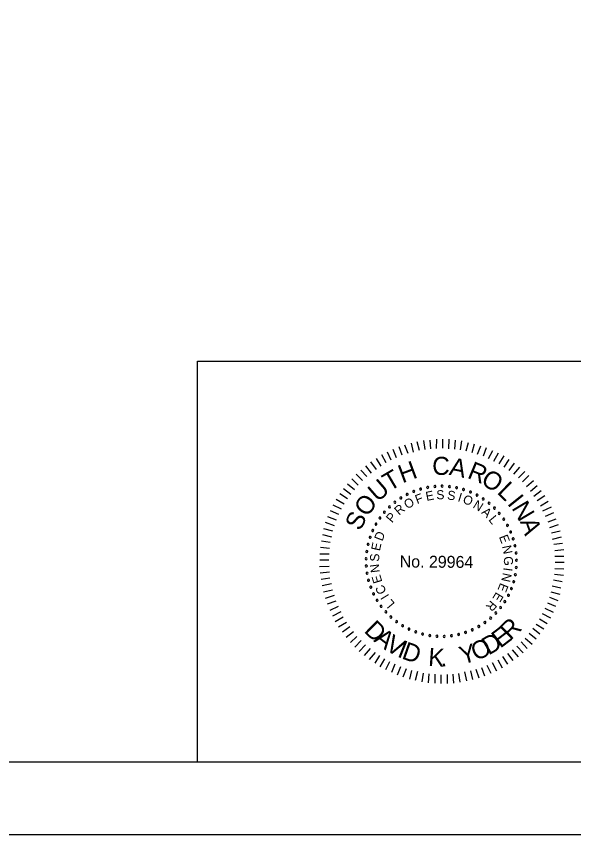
# Model space of a CAD drawing. Extents: x -121.2 to -24.9, y 6.4 to 66.3.
# Drawn here: x -64.11 to -53.92, y 6.35 to 21.33 of the extents above; entities that cross this region are included whole.
import ezdxf

# ---------------------------------------------------------------- set-up
doc = ezdxf.new("R2010")
doc.units = 0
for name, color, linetype in [('BR_BORDER LINES', 7, 'Continuous'), ('BR_TEXT', 7, 'Continuous'), ('Level 31', 7, 'Continuous')]:
    doc.layers.add(name, color=color, linetype=linetype)

msp = doc.modelspace()

# ---------------------------------------------------------------- linework, layer by layer
at = {"layer": 'BR_BORDER LINES'}
for p, q in [((-60.804, 15.017), (-46.496, 15.017)), ((-60.804, 7.683), (-60.804, 15.017)), ((-116.272, 7.683), (-26.496, 7.683))]:
    msp.add_line(p, q, dxfattribs=at)
at = {"layer": 'BR_TEXT'}
for p, q in [((-56.951, 13.326), (-57.009, 13.479)), ((-56.854, 13.352), (-56.89, 13.515)), ((-56.744, 13.379), (-56.782, 13.537)), ((-56.639, 13.398), (-56.663, 13.561)), ((-56.534, 13.409), (-56.544, 13.572)), ((-56.428, 13.415), (-56.427, 13.587)), ((-56.316, 13.421), (-56.315, 13.586)), ((-56.204, 13.413), (-56.198, 13.585)), ((-56.097, 13.405), (-56.084, 13.568)), ((-55.994, 13.393), (-55.965, 13.555)), ((-55.886, 13.372), (-55.848, 13.529)), ((-55.777, 13.343), (-55.734, 13.505)), ((-57.258, 13.202), (-57.328, 13.351)), ((-57.16, 13.247), (-57.223, 13.396)), ((-57.056, 13.292), (-57.112, 13.448)), ((-55.679, 13.315), (-55.62, 13.468)), ((-55.574, 13.28), (-55.515, 13.435)), ((-55.478, 13.233), (-55.403, 13.381)), ((-55.382, 13.187), (-55.298, 13.335)), ((-57.445, 13.092), (-57.526, 13.236)), ((-57.35, 13.155), (-57.432, 13.3)), ((-55.282, 13.138), (-55.196, 13.281)), ((-55.193, 13.073), (-55.103, 13.216)), ((-57.617, 12.967), (-57.724, 13.101)), ((-57.528, 13.035), (-57.632, 13.171)), ((-55.104, 13.015), (-55.007, 13.149)), ((-55.018, 12.946), (-54.909, 13.078)), ((-57.783, 12.829), (-57.901, 12.947)), ((-57.705, 12.902), (-57.816, 13.021)), ((-54.934, 12.879), (-54.818, 12.997)), ((-54.859, 12.805), (-54.743, 12.921)), ((-57.929, 12.663), (-58.061, 12.767)), ((-57.862, 12.747), (-57.978, 12.86)), ((-54.784, 12.722), (-54.657, 12.833)), ((-54.712, 12.636), (-54.587, 12.738)), ((-58.056, 12.497), (-58.2, 12.585)), ((-57.998, 12.574), (-58.13, 12.681)), ((-54.648, 12.547), (-54.517, 12.651)), ((-58.121, 12.399), (-58.264, 12.485)), ((-54.589, 12.468), (-54.449, 12.554)), ((-54.531, 12.37), (-54.388, 12.453)), ((-58.168, 12.308), (-58.318, 12.382)), ((-54.483, 12.278), (-54.329, 12.35)), ((-58.261, 12.107), (-58.416, 12.166)), ((-58.214, 12.21), (-58.367, 12.278)), ((-54.436, 12.179), (-54.284, 12.244)), ((-54.391, 12.075), (-54.24, 12.131)), ((-58.294, 12), (-58.458, 12.061)), ((-54.355, 11.968), (-54.202, 12.026)), ((-58.346, 11.792), (-58.512, 11.835)), ((-58.326, 11.904), (-58.489, 11.945)), ((-54.329, 11.871), (-54.168, 11.909)), ((-58.374, 11.696), (-58.536, 11.718)), ((-54.307, 11.759), (-54.146, 11.799)), ((-54.285, 11.663), (-54.127, 11.682)), ((-58.386, 11.587), (-58.551, 11.606)), ((-54.267, 11.553), (-54.105, 11.57)), ((-58.394, 11.481), (-58.566, 11.483)), ((-54.264, 11.447), (-54.103, 11.446)), ((-58.396, 11.257), (-58.568, 11.254)), ((-58.4, 11.372), (-58.567, 11.373)), ((-54.258, 11.338), (-54.095, 11.336)), ((-58.39, 11.154), (-58.555, 11.135)), ((-54.271, 11.12), (-54.109, 11.098)), ((-54.265, 11.223), (-54.105, 11.217)), ((-58.379, 11.044), (-58.542, 11.02)), ((-58.353, 10.939), (-58.52, 10.904)), ((-54.29, 11.011), (-54.132, 10.984)), ((-58.335, 10.826), (-58.498, 10.789)), ((-54.338, 10.793), (-54.178, 10.753)), ((-54.314, 10.905), (-54.154, 10.867)), ((-58.304, 10.728), (-58.469, 10.672)), ((-54.366, 10.695), (-54.213, 10.637)), ((-58.273, 10.625), (-58.429, 10.569)), ((-58.228, 10.526), (-58.382, 10.454)), ((-54.45, 10.495), (-54.3, 10.42)), ((-54.403, 10.593), (-54.253, 10.534)), ((-58.183, 10.429), (-58.335, 10.35)), ((-54.499, 10.399), (-54.346, 10.318)), ((-58.138, 10.331), (-58.283, 10.247)), ((-58.075, 10.232), (-58.22, 10.148)), ((-54.608, 10.203), (-54.469, 10.117)), ((-54.548, 10.301), (-54.407, 10.215)), ((-58.018, 10.153), (-58.152, 10.056)), ((-57.95, 10.064), (-58.084, 9.959)), ((-54.733, 10.037), (-54.61, 9.931)), ((-54.668, 10.126), (-54.539, 10.026)), ((-57.885, 9.974), (-58.002, 9.865)), ((-57.808, 9.904), (-57.927, 9.784)), ((-54.807, 9.948), (-54.682, 9.837)), ((-57.73, 9.824), (-57.844, 9.701)), ((-57.644, 9.754), (-57.753, 9.629)), ((-54.959, 9.801), (-54.846, 9.676)), ((-54.883, 9.88), (-54.77, 9.758)), ((-57.555, 9.685), (-57.662, 9.558)), ((-57.473, 9.627), (-57.557, 9.488)), ((-55.222, 9.608), (-55.134, 9.468)), ((-55.132, 9.665), (-55.037, 9.536)), ((-55.044, 9.733), (-54.938, 9.606)), ((-57.38, 9.567), (-57.464, 9.423)), ((-57.289, 9.513), (-57.361, 9.365)), ((-57.191, 9.467), (-57.256, 9.319)), ((-55.509, 9.453), (-55.437, 9.304)), ((-55.413, 9.498), (-55.331, 9.348)), ((-55.311, 9.55), (-55.228, 9.405)), ((-57.088, 9.42), (-57.147, 9.27)), ((-56.983, 9.387), (-57.044, 9.232)), ((-56.888, 9.354), (-56.925, 9.197)), ((-56.778, 9.335), (-56.818, 9.171)), ((-56.673, 9.305), (-56.699, 9.149)), ((-56.568, 9.292), (-56.58, 9.128)), ((-56.462, 9.285), (-56.464, 9.12)), ((-56.131, 9.289), (-56.121, 9.124)), ((-56.028, 9.299), (-56.001, 9.143)), ((-55.92, 9.328), (-55.884, 9.163)), ((-55.81, 9.346), (-55.77, 9.187)), ((-55.711, 9.377), (-55.655, 9.221)), ((-55.606, 9.408), (-55.55, 9.256)), ((-56.35, 9.277), (-56.352, 9.114)), ((-56.238, 9.283), (-56.235, 9.118))]:
    msp.add_line(p, q, dxfattribs=at)
for centre, start, end in [((-56.46, 12.723), 5.0653, 185.0653), ((-56.328, 12.728), 359.5268, 179.5268), ((-56.195, 12.72), 353.9884, 173.9884), ((-56.968, 12.577), 27.2191, 207.2191), ((-56.968, 12.577), 207.2191, 27.2191), ((-56.847, 12.632), 21.6807, 201.6807), ((-56.847, 12.632), 201.6807, 21.6807), ((-56.721, 12.674), 16.1422, 196.1422), ((-56.721, 12.674), 196.1422, 16.1422), ((-56.592, 12.705), 10.6038, 190.6038), ((-56.592, 12.705), 190.6038, 10.6038), ((-56.46, 12.723), 185.0653, 5.0653), ((-56.328, 12.728), 179.5268, 359.5268), ((-56.195, 12.72), 173.9884, 353.9884), ((-56.064, 12.699), 348.4499, 168.4499), ((-56.064, 12.699), 168.4499, 348.4499), ((-55.935, 12.666), 162.9114, 342.9114), ((-55.935, 12.666), 342.9114, 162.9114), ((-55.81, 12.621), 157.373, 337.373), ((-55.81, 12.621), 337.373, 157.373), ((-55.69, 12.564), 331.8345, 151.8345), ((-57.192, 12.434), 38.2961, 218.2961), ((-57.192, 12.434), 218.2961, 38.2961), ((-57.083, 12.511), 32.7576, 212.7576), ((-57.083, 12.511), 212.7576, 32.7576), ((-55.69, 12.564), 151.8345, 331.8345), ((-55.576, 12.495), 146.2961, 326.2961), ((-55.576, 12.495), 326.2961, 146.2961), ((-55.47, 12.416), 320.7576, 140.7576), ((-57.292, 12.347), 43.8345, 223.8345), ((-57.292, 12.347), 223.8345, 43.8345), ((-55.47, 12.416), 140.7576, 320.7576), ((-55.371, 12.327), 135.2191, 315.2191), ((-55.371, 12.327), 315.2191, 135.2191), ((-57.465, 12.145), 54.9114, 234.9114), ((-57.465, 12.145), 234.9114, 54.9114), ((-57.384, 12.25), 49.373, 229.373), ((-57.384, 12.25), 229.373, 49.373), ((-55.282, 12.229), 129.6807, 309.6807), ((-55.282, 12.229), 309.6807, 129.6807), ((-55.202, 12.122), 124.1422, 304.1422), ((-55.202, 12.122), 304.1422, 124.1422), ((-57.537, 12.033), 60.4499, 240.4499), ((-57.537, 12.033), 240.4499, 60.4499), ((-55.133, 12.009), 118.6038, 298.6038), ((-55.133, 12.009), 298.6038, 118.6038), ((-57.597, 11.915), 65.9884, 245.9884), ((-57.597, 11.915), 245.9884, 65.9884), ((-55.075, 11.889), 113.0653, 293.0653), ((-55.075, 11.889), 293.0653, 113.0653), ((-57.681, 11.663), 77.0653, 257.0653), ((-57.681, 11.663), 257.0653, 77.0653), ((-57.645, 11.791), 71.5268, 251.5268), ((-57.645, 11.791), 251.5268, 71.5268), ((-55.029, 11.764), 107.5268, 287.5268), ((-55.029, 11.764), 287.5268, 107.5268), ((-57.705, 11.532), 82.6038, 262.6038), ((-57.705, 11.532), 262.6038, 82.6038), ((-54.996, 11.636), 101.9884, 281.9884), ((-54.996, 11.636), 281.9884, 101.9884), ((-57.716, 11.4), 88.1422, 268.1422), ((-57.716, 11.4), 268.1422, 88.1422), ((-54.975, 11.504), 96.4499, 276.4499), ((-54.967, 11.372), 90.9114, 270.9114), ((-54.975, 11.504), 276.4499, 96.4499), ((-54.967, 11.372), 270.9114, 90.9114), ((-57.714, 11.267), 93.6807, 273.6807), ((-57.714, 11.267), 273.6807, 93.6807), ((-54.971, 11.239), 85.373, 265.373), ((-54.971, 11.239), 265.373, 85.373), ((-57.7, 11.135), 99.2191, 279.2191), ((-57.7, 11.135), 279.2191, 99.2191), ((-54.989, 11.107), 79.8345, 259.8345), ((-54.989, 11.107), 259.8345, 79.8345), ((-57.672, 11.005), 104.7576, 284.7576), ((-57.672, 11.005), 284.7576, 104.7576), ((-55.019, 10.978), 74.2961, 254.2961), ((-55.019, 10.978), 254.2961, 74.2961), ((-57.632, 10.878), 110.2961, 290.2961), ((-57.632, 10.878), 290.2961, 110.2961), ((-55.061, 10.852), 68.7576, 248.7576), ((-55.061, 10.852), 248.7576, 68.7576), ((-57.581, 10.756), 115.8345, 295.8345), ((-57.581, 10.756), 295.8345, 115.8345), ((-57.517, 10.639), 121.373, 301.373), ((-57.517, 10.639), 301.373, 121.373), ((-55.181, 10.615), 57.6807, 237.6807), ((-55.115, 10.731), 63.2191, 243.2191), ((-55.115, 10.731), 243.2191, 63.2191), ((-57.443, 10.529), 126.9114, 306.9114), ((-57.443, 10.529), 306.9114, 126.9114), ((-55.258, 10.507), 52.1422, 232.1422), ((-55.258, 10.507), 232.1422, 52.1422), ((-55.181, 10.615), 237.6807, 57.6807), ((-57.358, 10.426), 132.4499, 312.4499), ((-57.358, 10.426), 312.4499, 132.4499), ((-57.264, 10.333), 137.9884, 317.9884), ((-57.264, 10.333), 317.9884, 137.9884), ((-55.344, 10.406), 46.6038, 226.6038), ((-55.344, 10.406), 226.6038, 46.6038), ((-57.161, 10.248), 143.5268, 323.5268), ((-57.161, 10.248), 323.5268, 143.5268), ((-57.051, 10.174), 149.0653, 329.0653), ((-57.051, 10.174), 329.0653, 149.0653), ((-55.545, 10.232), 35.5268, 215.5268), ((-55.545, 10.232), 215.5268, 35.5268), ((-55.44, 10.314), 41.0653, 221.0653), ((-55.44, 10.314), 221.0653, 41.0653), ((-56.934, 10.112), 154.6038, 334.6038), ((-56.934, 10.112), 334.6038, 154.6038), ((-56.811, 10.06), 160.1422, 340.1422), ((-56.811, 10.06), 340.1422, 160.1422), ((-56.684, 10.021), 345.6807, 165.6807), ((-55.899, 10.051), 18.9114, 198.9114), ((-55.899, 10.051), 198.9114, 18.9114), ((-55.775, 10.1), 24.4499, 204.4499), ((-55.775, 10.1), 204.4499, 24.4499), ((-55.657, 10.16), 29.9884, 209.9884), ((-55.657, 10.16), 209.9884, 29.9884), ((-56.684, 10.021), 165.6807, 345.6807), ((-56.554, 9.994), 351.2191, 171.2191), ((-56.554, 9.994), 171.2191, 351.2191), ((-56.422, 9.98), 356.7576, 176.7576), ((-56.422, 9.98), 176.7576, 356.7576), ((-56.289, 9.978), 2.2961, 182.2961), ((-56.289, 9.978), 182.2961, 2.2961), ((-56.157, 9.99), 7.8345, 187.8345), ((-56.157, 9.99), 187.8345, 7.8345), ((-56.026, 10.014), 13.373, 193.373), ((-56.026, 10.014), 193.373, 13.373)]:
    msp.add_arc(centre, 0.0187, start, end, dxfattribs=at)
at = {"layer": 'Level 31'}
msp.add_lwpolyline([(-121.161, 6.35), (-25.161, 6.35), (-25.161, 65.017), (-121.161, 65.017)], close=True, dxfattribs=at)

# ---------------------------------------------------------------- texts
at = {"layer": 'BR_TEXT'}
for s, height, rotation, p in [('H', 0.331, 20.3637, (-57.055, 12.779)), ('C', 0.331, 359.5482, (-56.51, 12.935)), ('A', 0.331, 348.1981, (-56.213, 12.937)), ('T', 0.331, 30.4992, (-57.29, 12.626)), ('R', 0.331, 337.4344, (-55.884, 12.884)), ('O', 0.33, 326.5869, (-55.638, 12.786)), ('U', 0.331, 40.8022, (-57.506, 12.426)), ('L', 0.331, 315.9488, (-55.338, 12.605)), ('F', 0.166, 20.6127, (-56.785, 12.398)), ('E', 0.166, 11.4103, (-56.611, 12.456)), ('S', 0.166, 2.208, (-56.431, 12.485)), ('S', 0.166, 352.6608, (-56.241, 12.485)), ('I', 0.166, 343.1136, (-56.053, 12.453)), ('I', 0.331, 308.6613, (-55.148, 12.407)), ('O', 0.331, 52.0267, (-57.705, 12.149)), ('O', 0.166, 30.8477, (-56.965, 12.302)), ('O', 0.166, 338.4392, (-55.964, 12.426)), ('N', 0.166, 328.2042, (-55.778, 12.342)), ('N', 0.331, 300.7037, (-55.066, 12.329)), ('R', 0.166, 40.3949, (-57.115, 12.185)), ('A', 0.166, 318.657, (-55.621, 12.235)), ('S', 0.33, 63.2511, (-57.826, 11.894)), ('P', 0.166, 49.9421, (-57.243, 12.045)), ('L', 0.166, 309.4546, (-55.488, 12.109)), ('A', 0.331, 289.4792, (-54.908, 12.081)), ('D', 0.166, 69.0364, (-57.421, 11.711)), ('E', 0.166, 291.049, (-55.291, 11.801)), ('E', 0.166, 78.2388, (-57.466, 11.533)), ('N', 0.166, 281.8466, (-55.232, 11.628)), ('S', 0.166, 87.786, (-57.481, 11.344)), ('No. 29964', 0.218, 359.5268, (-57.104, 11.241)), ('G', 0.166, 272.2995, (-55.201, 11.441)), ('N', 0.166, 97.3332, (-57.464, 11.154)), ('E', 0.166, 106.5355, (-57.419, 10.977)), ('N', 0.166, 257.7339, (-55.214, 11.151)), ('I', 0.166, 262.4084, (-55.202, 11.244)), ('E', 0.166, 248.1867, (-55.262, 10.968)), ('C', 0.166, 116.4266, (-57.339, 10.797)), ('E', 0.166, 238.9844, (-55.337, 10.8)), ('I', 0.166, 121.1011, (-57.291, 10.717)), ('L', 0.166, 129.9595, (-57.183, 10.578)), ('R', 0.166, 229.782, (-55.437, 10.647)), ('D', 0.329, 315.4053, (-57.771, 10.07)), ('R', 0.329, 44.5947, (-55.075, 9.895)), ('A', 0.329, 322.8377, (-57.593, 9.895)), ('E', 0.329, 37.5339, (-55.263, 9.751)), ('V', 0.329, 330.5179, (-57.387, 9.739)), ('I', 0.329, 338.1981, (-57.163, 9.613)), ('O', 0.329, 22.4212, (-55.717, 9.527)), ('D', 0.329, 30.1015, (-55.479, 9.626)), ('D', 0.329, 340.7995, (-57.083, 9.577)), ('K', 0.329, 356.098, (-56.589, 9.442)), ('Y', 0.329, 14.8649, (-55.962, 9.462)), ('.', 0.329, 3.1588, (-56.353, 9.426))]:
    msp.add_text(s, height=height, rotation=rotation, dxfattribs=at).set_placement(p)

doc.saveas('drawing.dxf')
